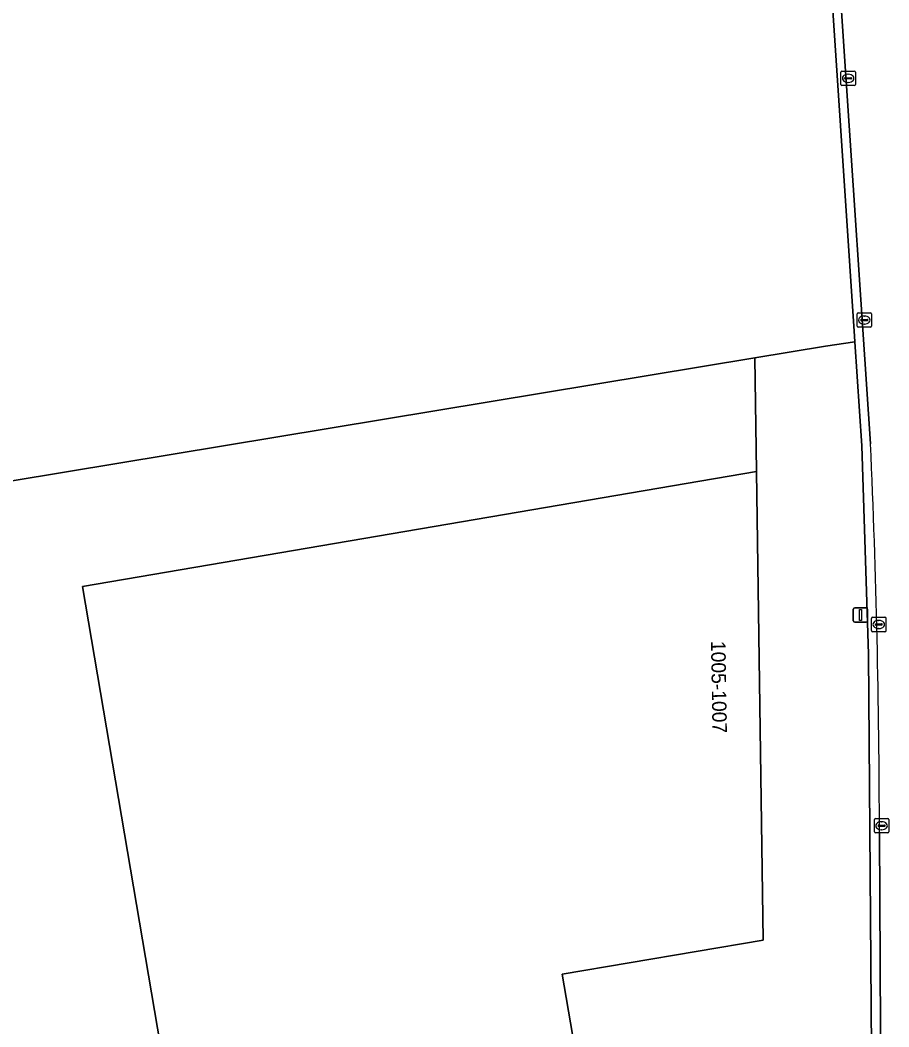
# Model space of a CAD drawing. Extents: x 154324 to 155744, y 382937 to 384188.
# Drawn here: x 155011.6 to 155071.8, y 383293.7 to 383363.4 of the extents above; entities that cross this region are included whole.
import ezdxf

# ---------------------------------------------------------------- set-up
doc = ezdxf.new("R2010")
doc.units = 0
for name, color, linetype in [('IMGEO_Erf', 7, 'Continuous'), ('IMGEO_Grasland_agrarisch', 7, 'Continuous'), ('IMGEO_Kolk', 7, 'Continuous'), ('IMGEO_Lichtmast', 7, 'Continuous'), ('IMGEO_Pand', 7, 'Continuous'), ('IMGEO_Pand_nummerreeks', 7, 'Continuous'), ('IMGEO_Parkeervlak_open', 7, 'Continuous'), ('IMGEO_Rijbaan_lokaal_gesloten', 7, 'Continuous'), ('IMGEO_Rijbaan_lokaal_open', 7, 'Continuous')]:
    doc.layers.add(name, color=color, linetype=linetype)

msp = doc.modelspace()

# ---------------------------------------------------------------- linework, layer by layer
at = {"layer": 'IMGEO_Erf'}
msp.add_lwpolyline([(155007.491, 383271.866), (155014.059, 383233.409), (155019.588, 383236.524), (155012.696, 383277.028), (155023.637, 383278.886), (155015.928, 383324.201), (155062.639, 383332.154), (155062.526, 383340.029), (155003.646, 383330.283)], dxfattribs=at)
at = {"layer": 'IMGEO_Grasland_agrarisch'}
msp.add_lwpolyline([(154995.109, 383380.559), (154999.878, 383352.447), (155000.868, 383346.436), (155003.646, 383330.283), (155062.526, 383340.029), (155067.422, 383340.839), (155069.458, 383341.15), (155069.432, 383341.538), (155066.213, 383389.857)], dxfattribs=at)
at = {"layer": 'IMGEO_Kolk'}
for p, q in [((155068.486, 383358.987), (155068.486, 383359.839)), ((155068.561, 383359.913), (155069.413, 383359.913)), ((155068.745, 383359.407), (155068.745, 383359.419)), ((155069.183, 383359.37), (155068.785, 383359.37)), ((155068.788, 383359.456), (155069.186, 383359.456)), ((155068.974, 383359.693), (155068.999, 383359.693)), ((155069.229, 383359.419), (155069.229, 383359.407)), ((155069.487, 383359.839), (155069.487, 383358.987)), ((155069.413, 383358.913), (155068.561, 383358.913)), ((155068.997, 383359.133), (155068.972, 383359.133)), ((155069.607, 383342.232), (155069.607, 383343.084)), ((155069.682, 383343.158), (155070.534, 383343.158)), ((155069.866, 383342.652), (155069.866, 383342.664)), ((155069.909, 383342.701), (155070.307, 383342.701)), ((155070.095, 383342.938), (155070.12, 383342.938)), ((155070.35, 383342.664), (155070.35, 383342.652)), ((155070.608, 383343.084), (155070.608, 383342.232)), ((155070.534, 383342.158), (155069.682, 383342.158)), ((155070.304, 383342.615), (155069.906, 383342.615)), ((155070.118, 383342.378), (155070.093, 383342.378)), ((155070.61, 383321.133), (155070.61, 383321.985)), ((155070.685, 383322.059), (155071.537, 383322.059)), ((155071.098, 383321.839), (155071.123, 383321.839)), ((155071.611, 383321.985), (155071.611, 383321.133)), ((155071.537, 383321.059), (155070.685, 383321.059)), ((155070.869, 383321.553), (155070.869, 383321.565)), ((155071.307, 383321.516), (155070.909, 383321.516)), ((155070.912, 383321.602), (155071.31, 383321.602)), ((155071.121, 383321.279), (155071.096, 383321.279)), ((155071.353, 383321.565), (155071.353, 383321.553)), ((155070.804, 383307.184), (155070.804, 383308.036)), ((155070.879, 383308.11), (155071.731, 383308.11)), ((155071.292, 383307.89), (155071.317, 383307.89)), ((155071.805, 383308.036), (155071.805, 383307.184)), ((155071.731, 383307.11), (155070.879, 383307.11)), ((155071.063, 383307.604), (155071.063, 383307.616)), ((155071.501, 383307.567), (155071.103, 383307.567)), ((155071.106, 383307.653), (155071.504, 383307.653)), ((155071.315, 383307.33), (155071.29, 383307.33)), ((155071.547, 383307.616), (155071.547, 383307.604))]:
    msp.add_line(p, q, dxfattribs=at)
for points in [[(155068.486, 383358.987), (155068.486, 383359.839)], [(155068.561, 383359.913), (155069.413, 383359.913)], [(155069.487, 383359.839), (155069.487, 383358.987)], [(155069.413, 383358.913), (155068.561, 383358.913)], [(155069.607, 383342.232), (155069.607, 383343.084)], [(155069.682, 383343.158), (155070.534, 383343.158)], [(155070.608, 383343.084), (155070.608, 383342.232)], [(155070.534, 383342.158), (155069.682, 383342.158)], [(155070.61, 383321.133), (155070.61, 383321.985)], [(155070.685, 383322.059), (155071.537, 383322.059)], [(155071.611, 383321.985), (155071.611, 383321.133)], [(155071.537, 383321.059), (155070.685, 383321.059)], [(155070.804, 383307.184), (155070.804, 383308.036)], [(155070.879, 383308.11), (155071.731, 383308.11)], [(155071.805, 383308.036), (155071.805, 383307.184)], [(155071.731, 383307.11), (155070.879, 383307.11)]]:
    msp.add_lwpolyline(points, dxfattribs=at)
for centre, radius, start, end in [((155068.563, 383359.837), 0.0765, 91.55205, 178.44795), ((155068.563, 383359.837), 0.0765, 91.55205, 178.44795), ((155068.785, 383359.416), 0.0403, 85.87752, 175.75265), ((155068.782, 383359.406), 0.0366, 178.93798, 274.71019), ((155069.186, 383359.413), 0.043, 264.86636, 352.45326), ((155069.19, 383359.418), 0.0386, 1.73085, 96.63898), ((155069.411, 383359.837), 0.0765, 1.55205, 88.44795), ((155069.411, 383359.837), 0.0765, 1.55205, 88.44795), ((155068.563, 383358.989), 0.0765, 181.55205, 268.44795), ((155068.563, 383358.989), 0.0765, 181.55205, 268.44795), ((155069.411, 383358.989), 0.0765, 271.55205, 358.44795), ((155069.411, 383358.989), 0.0765, 271.55205, 358.44795), ((155069.684, 383343.082), 0.0765, 91.55205, 178.44795), ((155069.684, 383343.082), 0.0765, 91.55205, 178.44795), ((155069.906, 383342.661), 0.0403, 85.87752, 175.75265), ((155069.903, 383342.651), 0.0366, 178.93798, 274.71019), ((155070.307, 383342.658), 0.043, 264.86636, 352.45326), ((155070.311, 383342.663), 0.0386, 1.73085, 96.63898), ((155070.532, 383343.082), 0.0765, 1.55205, 88.44795), ((155070.532, 383343.082), 0.0765, 1.55205, 88.44795), ((155069.684, 383342.234), 0.0765, 181.55205, 268.44795), ((155069.684, 383342.234), 0.0765, 181.55205, 268.44795), ((155070.532, 383342.234), 0.0765, 271.55205, 358.44795), ((155070.532, 383342.234), 0.0765, 271.55205, 358.44795), ((155070.687, 383321.983), 0.0765, 91.55205, 178.44795), ((155070.687, 383321.983), 0.0765, 91.55205, 178.44795), ((155071.535, 383321.983), 0.0765, 1.55205, 88.44795), ((155071.535, 383321.983), 0.0765, 1.55205, 88.44795), ((155070.687, 383321.135), 0.0765, 181.55205, 268.44795), ((155070.687, 383321.135), 0.0765, 181.55205, 268.44795), ((155070.909, 383321.562), 0.0403, 85.87752, 175.75265), ((155070.906, 383321.552), 0.0366, 178.93798, 274.71019), ((155071.31, 383321.559), 0.043, 264.86636, 352.45326), ((155071.314, 383321.564), 0.0386, 1.73085, 96.63898), ((155071.535, 383321.135), 0.0765, 271.55205, 358.44795), ((155071.535, 383321.135), 0.0765, 271.55205, 358.44795), ((155070.881, 383308.034), 0.0765, 91.55205, 178.44795), ((155070.881, 383308.034), 0.0765, 91.55205, 178.44795), ((155071.729, 383308.034), 0.0765, 1.55205, 88.44795), ((155071.729, 383308.034), 0.0765, 1.55205, 88.44795), ((155070.881, 383307.186), 0.0765, 181.55205, 268.44795), ((155070.881, 383307.186), 0.0765, 181.55205, 268.44795), ((155071.103, 383307.613), 0.0403, 85.87752, 175.75265), ((155071.1, 383307.603), 0.0366, 178.93798, 274.71019), ((155071.504, 383307.61), 0.043, 264.86636, 352.45326), ((155071.508, 383307.615), 0.0386, 1.73085, 96.63898), ((155071.729, 383307.186), 0.0765, 271.55205, 358.44795), ((155071.729, 383307.186), 0.0765, 271.55205, 358.44795)]:
    msp.add_arc(centre, radius, start, end, dxfattribs=at)
for centre, major_axis, ratio, start_param, end_param in [((155068.973, 383359.413), (-0.387, 0.002), 0.722429, 4.712389, 7.853982), ((155068.998, 383359.413), (-0.39, 0.002), 0.717154, 1.570796, 4.712389), ((155070.094, 383342.658), (-0.387, 0.002), 0.722429, 4.712389, 7.853982), ((155070.119, 383342.658), (-0.39, 0.002), 0.717154, 1.570796, 4.712389), ((155071.097, 383321.559), (-0.387, 0.002), 0.722429, 4.712389, 7.853982), ((155071.122, 383321.559), (-0.39, 0.002), 0.717154, 1.570796, 4.712389), ((155071.291, 383307.61), (-0.387, 0.002), 0.722429, 4.712389, 7.853982), ((155071.316, 383307.61), (-0.39, 0.002), 0.717154, 1.570796, 4.712389)]:
    msp.add_ellipse(centre, major_axis=major_axis, ratio=ratio, start_param=start_param, end_param=end_param, dxfattribs=at)
at = {"layer": 'IMGEO_Lichtmast'}
for p, q in [((155069.346, 383321.813), (155069.346, 383322.613)), ((155069.346, 383322.613), (155069.346, 383321.813)), ((155069.446, 383322.713), (155070.236, 383322.713)), ((155070.236, 383322.713), (155069.446, 383322.713)), ((155070.336, 383322.613), (155070.336, 383321.813)), ((155070.336, 383321.813), (155070.336, 383322.613)), ((155070.236, 383321.713), (155069.446, 383321.713)), ((155069.446, 383321.713), (155070.236, 383321.713))]:
    msp.add_line(p, q, dxfattribs=at)
msp.add_lwpolyline([(155069.766, 383322.588), (155069.916, 383322.588), (155069.916, 383321.838), (155069.766, 383321.838), (155069.766, 383322.588)], dxfattribs=at)
for centre, start, end in [((155069.446, 383322.613), 90, 180), ((155069.446, 383322.613), 90, 180), ((155070.236, 383322.613), 0, 90), ((155070.236, 383322.613), 360, 90), ((155069.446, 383321.813), 180, 270), ((155069.446, 383321.813), 180, 270), ((155070.236, 383321.813), 270, 0), ((155070.236, 383321.813), 270, 0)]:
    msp.add_arc(centre, 0.1, start, end, dxfattribs=at)
at = {"layer": 'IMGEO_Pand'}
msp.add_lwpolyline([(155063.103, 383299.681), (155062.639, 383332.154), (155015.928, 383324.201), (155023.637, 383278.886), (155063.332, 383285.627), (155063.294, 383286.173), (155051.414, 383284.155), (155051.381, 383284.351), (155051.339, 383284.597), (155050.501, 383289.532), (155050.459, 383289.779), (155049.179, 383297.317)], close=True, dxfattribs=at)
at = {"layer": 'IMGEO_Parkeervlak_open'}
msp.add_lwpolyline([(155070.4, 383319.494), (155069.938, 383333.947), (155069.458, 383341.15), (155067.422, 383340.839), (155062.526, 383340.029), (155062.639, 383332.154), (155063.103, 383299.681), (155049.179, 383297.317), (155050.459, 383289.779), (155050.501, 383289.532), (155051.339, 383284.597), (155051.381, 383284.351), (155051.414, 383284.155), (155063.294, 383286.173), (155070.643, 383287.421), (155070.638, 383289.04)], close=True, dxfattribs=at)
at = {"layer": 'IMGEO_Rijbaan_lokaal_gesloten'}
for points in [[(155066.805, 383389.917), (155070.546, 383334.082)], [(155071.154, 383307.067), (155071.247, 383289.042), (155077.212, 383288.99), (155077.149, 383306.965)]]:
    msp.add_lwpolyline(points, dxfattribs=at)
msp.add_arc((154441.799, 383306.417), 629.355, 0.059169, 2.519395, dxfattribs=at)
at = {"layer": 'IMGEO_Rijbaan_lokaal_open'}
for points in [[(155059.439, 383453.463), (155046.503, 383530.572), (155016.871, 383707.197), (155016.277, 383707.107), (155024.164, 383660.104), (155045.918, 383530.449), (155058.846, 383453.397), (155060.487, 383443.041), (155061.613, 383435.27), (155063.03, 383424.403), (155063.139, 383423.564), (155064.659, 383408.986), (155065.341, 383401.33), (155065.709, 383396.485), (155066.213, 383389.857), (155069.432, 383341.538), (155069.458, 383341.15), (155069.938, 383333.947), (155070.4, 383319.494), (155070.638, 383289.04), (155071.247, 383289.042), (155071.154, 383307.067)], [(155070.546, 383334.082), (155066.805, 383389.917)]]:
    msp.add_lwpolyline(points, dxfattribs=at)
msp.add_arc((154441.799, 383306.417), 629.355, 0.059169, 2.519395, dxfattribs=at)

# ---------------------------------------------------------------- texts
at = {"layer": 'IMGEO_Pand_nummerreeks'}
msp.add_text('1005-1007', height=1, rotation=270.93779, dxfattribs=at).set_placement((155059.486, 383320.413))

doc.saveas('drawing.dxf')
